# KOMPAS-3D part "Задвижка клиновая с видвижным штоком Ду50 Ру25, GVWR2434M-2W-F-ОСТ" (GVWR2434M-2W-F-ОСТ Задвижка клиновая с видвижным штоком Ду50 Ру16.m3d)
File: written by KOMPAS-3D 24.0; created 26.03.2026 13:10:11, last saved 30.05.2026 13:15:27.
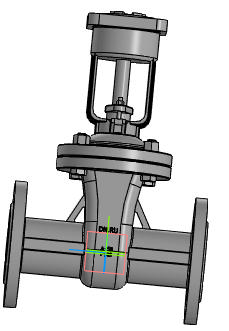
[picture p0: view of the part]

Document properties: Автор: R2D2; Полное имя файла: E:\Работа\Зайцев\GVWR2434M-2W-F-ОСТ Задвижка клиновая с выдвижным штоком DN.ru Ду50-300 Ру25\исходные материалы\DN50\GVWR2434M-2W-F-ОСТ Задвижка клиновая с видвижным штоком Ду50 Ру16.m3d

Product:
- Component [detail]: AS 1110 - M12 x 45  | qty 4  | pos. 2  | Комментарий: Болты и винты   шестигранные точные   метрические ISO; Автор: R2D2; additional columns: Сталь, мягкая; source file: AS 1110 - M12 x 45 AS 1110 - M12 x 45.m3d
- Component [detail]: ANSI B18.2.4.2M - M12x1,75 - 18  | designation ANSI B18.2.4.2M - M12x1,75  | qty 4  | pos. 3  | Комментарий: Типы метрических   шестигранных гаек   2; Автор: R2D2; additional columns: Сталь, мягкая; source file: ANSI B18.2.4.2M - M12x1,75 ANSI B18.2.4.2M - M12x1,75 - 18.m3d
- Component [detail]: ANSI B18.2.4.2M - M5x0,8 - 8  | designation ANSI B18.2.4.2M - M5x0,8  | qty 1  | pos. 4  | Комментарий: Типы метрических   шестигранных гаек   2; Автор: R2D2; additional columns: Сталь, мягкая; source file: ANSI B18.2.4.2M - M5x0,8 ANSI B18.2.4.2M - M5x0,8 - 8.m3d
- Component [detail]: Деталь1  | qty 1  | pos. 5  | Автор: R2D2; additional columns: Типовые; source file: 2.m3d
- Component [detail]: Фланец  | qty 1  | pos. 5  | Автор: R2D2; additional columns: Типовые; source file: Фланец DN50 PN25 D160 b18.m3d
- Component [detail]: Фланец  | designation 01  | qty 1  | pos. 6  | Автор: R2D2; additional columns: Типовые; source file: Фланец DN50 PN25 D160 b18.m3d
- Component [detail]: ANSI B18.2.4.2M - M5x0,8 - 8  | designation ANSI B18.2.4.2M - M5x0,8-01  | qty 1  | pos. 7  | Комментарий: Типы метрических   шестигранных гаек   2; Автор: R2D2; additional columns: Сталь, мягкая; source file: ANSI B18.2.4.2M - M5x0,8 ANSI B18.2.4.2M - M5x0,8 - 8.m3d
- Component [assembly]: DN50_3D_STEP  | designation Сборка  | qty 1  | Масса: 2.725126; Автор: R2D2; source file: Фланец А.a3d
- Body: Тело 1  | qty 1
    Масса: 21.070481
- Part/product: Задвижка клиновая с видвижным штоком Ду50 Ру25  | designation GVWR2434M-2W-F-ОСТ
    Масса: 13
    Раздел спецификации: Прочие изделия
    Примечание: D040-07586

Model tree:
1. Массив по концентрической сетке:1  (labels: Грань.Твердое тело1)  (4 pattern instances)
     Шаг 2 = 360
2. Скругление:1  (with: Ребро.Операция без истории:2)
     Радиус = 5
3. Элемент выдавливания:1  (with: Грань.Элемент выдавливания:1, Грань.Операция без истории:2)
     Расстояние 1 = 48.9137
4. Элемент выдавливания:2  (with: Грань.Элемент выдавливания:1)
     Расстояние 1 = 65.9137; Смещение 1 = 55
5. Элемент выдавливания:3  (with: Грань.Элемент выдавливания:1, Грань.Элемент вращения:1)
     Расстояние 1 = 46.6136
6. Элемент выдавливания:4  (with: Грань.Элемент выдавливания:1, Грань.Элемент вращения:1)
     Расстояние 1 = 44.9933
7. Скругление:2  (with: Ребро.Элемент выдавливания:3, Ребро.Элемент выдавливания:4)
     Радиус = 2
8. Эскиз:1
9. Элемент выдавливания:5  (with: Грань.Элемент выдавливания:1, Грань.Элемент вращения:1, Грань.Операция без истории:2)  (labels: Грань.Твердое тело1; Грань.Solid1; Solid1; Твердое тело1)
     Расстояние 1 = 46; Смещение 1 = 1; Расстояние = -125; Ориентация = 2; Ориентация = 2; Расстояние = -305

Referenced files in E:\Работа\Зайцев\GVWR2434M-2W-F-ОСТ Задвижка клиновая с выдвижным штоком DN.ru Ду50-300 Ру25\исходные материалы\DN50\: AS 1110 - M12 x 45 AS 1110 - M12 x 45.m3d, ANSI B18.2.4.2M - M12x1,75 ANSI B18.2.4.2M - M12x1,75 - 18.m3d, ANSI B18.2.4.2M - M5x0,8 ANSI B18.2.4.2M - M5x0,8 - 8.m3d, 2.m3d, Фланец А.a3d, Фланец DN50 PN25 D160 b18.m3d
Referenced files in E:\Работа\Зайцев\GVWR3131M-2W-F-S Задвижка клиновая с выдвижным штоком DN.ru Ду50-200 Ру63\DN50\исходные материалы\: ANSI B18.2.4.2M - M12x1,75 ANSI B18.2.4.2M - M12x1,75 - 18.m3d, AS 1110 - M12 x 45 AS 1110 - M12 x 45.m3d
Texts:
  GVWR2434M-2W-F-ОСТ
  Ду50
  GOST 26.020 Pr3
  Ру25
  AS 1110 - M12 x 45 AS 1110 - M12 x 45 (1)
  ANSI B18.2.4.2M - M12x1,75 ANSI B18.2.4.2M - M12x1,75 - 18 (1)
  ANSI B18.2.4.2M - M5x0,8 ANSI B18.2.4.2M - M5x0,8 - 8
  Деталь1 Деталь1
  ANSI B18.2.4.2M - M12x1,75 ANSI B18.2.4.2M - M12x1,75 - 18 (2)
  AS 1110 - M12 x 45 AS 1110 - M12 x 45 (2)
  ANSI B18.2.4.2M - M12x1,75 ANSI B18.2.4.2M - M12x1,75 - 18 (3)
  AS 1110 - M12 x 45 AS 1110 - M12 x 45 (3)
  ANSI B18.2.4.2M - M12x1,75 ANSI B18.2.4.2M - M12x1,75 - 18 (4)
  AS 1110 - M12 x 45 AS 1110 - M12 x 45 (4)
  ANSI B18.2.4.2M - M5x0,8-01 ANSI B18.2.4.2M - M5x0,8 - 8
  Сборка DN50_3D_STEP
  Ось Y.Начало координат
  Ось Z.Начало координат
  Плоскость ZX.Начало координат
  Плоскость XY.Начало координат
  Плоскость ZY.Начало координат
